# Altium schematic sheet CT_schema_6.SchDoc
size 278 x 236 mm
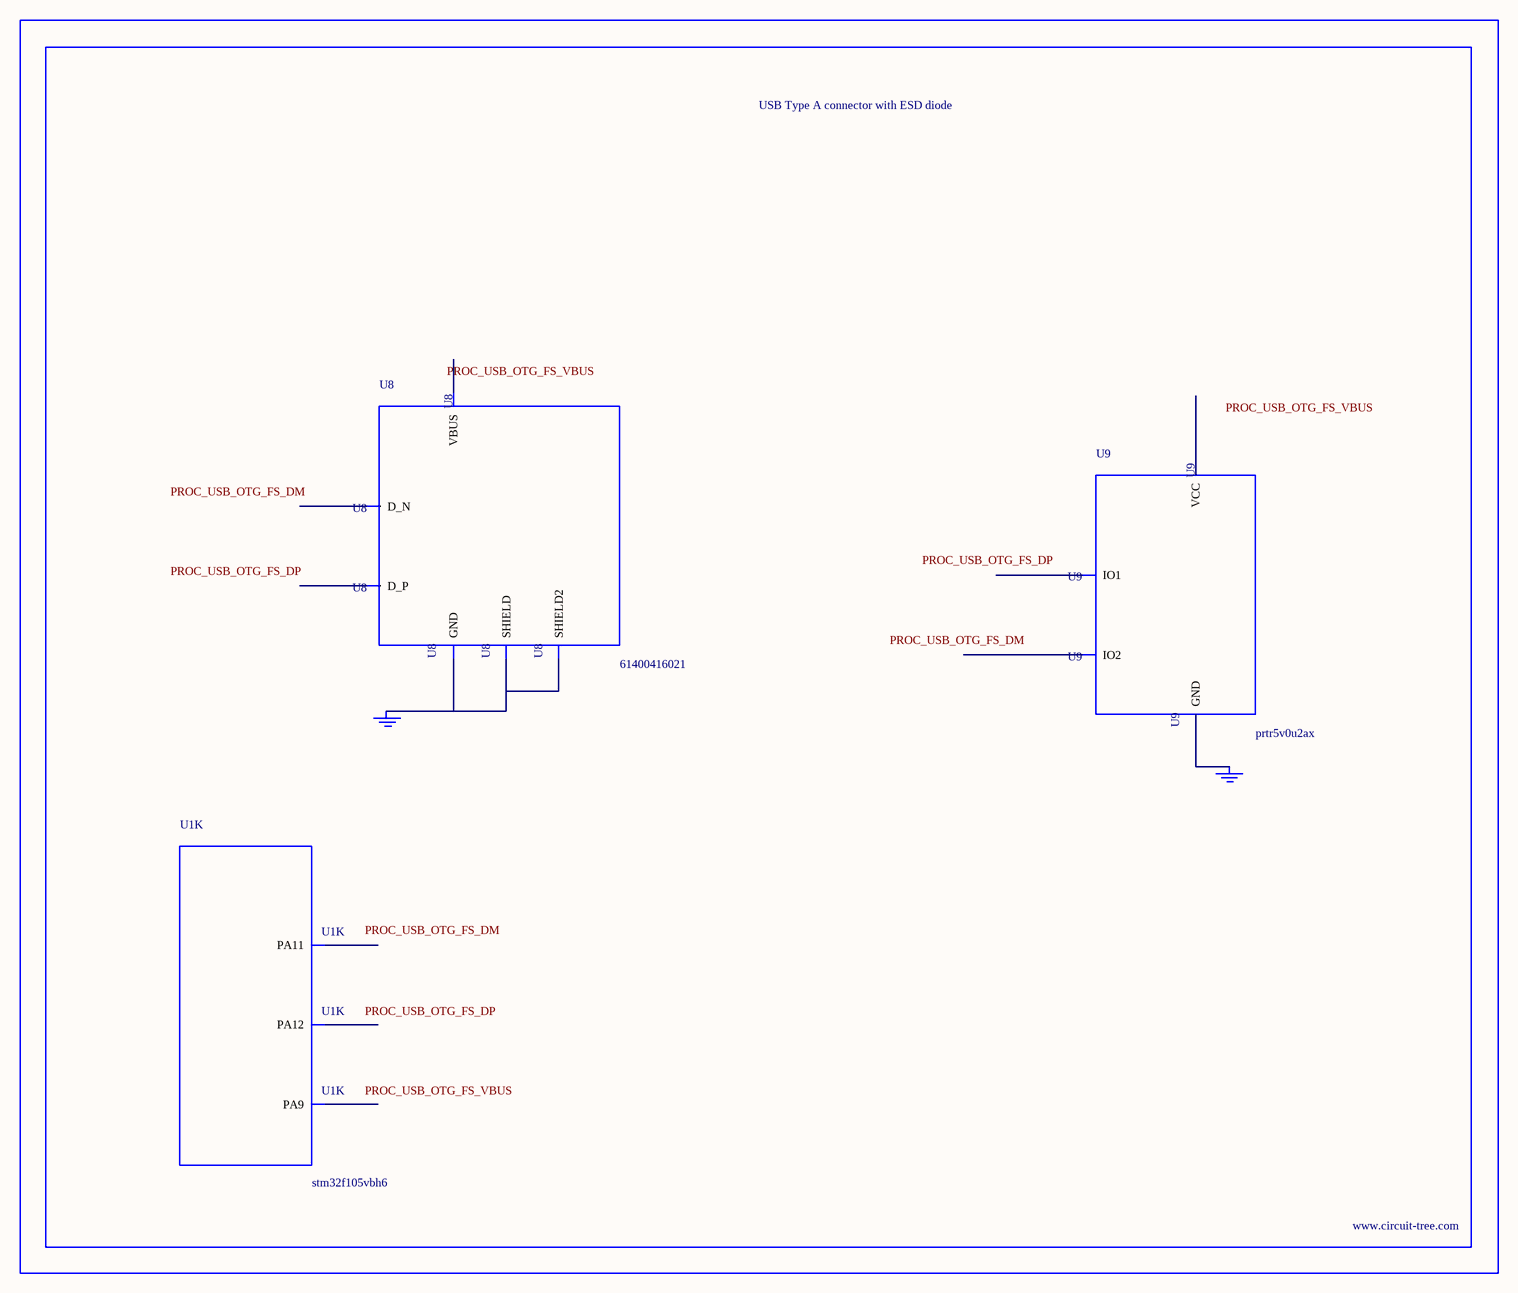
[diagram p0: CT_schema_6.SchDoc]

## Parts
BORDER5  (no value)
GND_INSTANCE_5_0  (no value)
GND_INSTANCE_5_1  (no value)
U1  stm32f105vbh6  [LFBGA100]  (part K of 11)
U8  61400416021  [USB-A-H]
U9  prtr5v0u2ax  [SOT143B]

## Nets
NetGND_INSTANCE_5_0_0: GND_INSTANCE_5_0.0(GND) U8.4(GND) U8.5(SHIELD) U8.6(SHIELD2)
NetGND_INSTANCE_5_1_0: GND_INSTANCE_5_1.0(GND) U9.1(GND)

Not connected (* = marked no-connect by the designer): U1 B10(PA12) C9(PA9) C10(PA11); U8 1(VBUS) 2(D_N) 3(D_P); U9 2(IO1) 3(IO2) 4(VCC)

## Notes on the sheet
- Labels drawn without touching a wire or pin: PROC_USB_OTG_FS_DM, PROC_USB_OTG_FS_DP, PROC_USB_OTG_FS_VBUS

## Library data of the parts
BORDER5 = BORDER_PAGE5
GND_INSTANCE_5_0 GND_INSTANCE_5_1 = GND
